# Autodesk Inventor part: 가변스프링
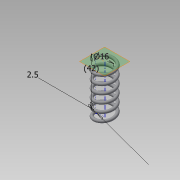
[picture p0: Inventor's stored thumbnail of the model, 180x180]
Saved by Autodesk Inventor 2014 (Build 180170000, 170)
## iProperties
Created: 2015-05
Part Number: 가변스프링
Material: Generic
Document SubType Name: Modeling
Designer: Administrator
Density: 1 g/cm^3
Appearance: Default
Mass: 1.46191 g
Surface Area: 23.7467 cm^2
Volume: 1.46191 cm^3
Author: Administrator
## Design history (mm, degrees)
sketch "스케치1"
  geometry: L1 (0, 0)-(-8, 0); L2 (-8, 0)-(-8, 41.999); L3 (-8, 41.999)-(0, 41.999); L4 (0, 41.999)-(0, 0); C1 r 1.25 at (-8, 0)
  constraints: 8 end point, 2 parallel, 1 centre point, 1 coincident, 1 horizontal, 1 perpendicular
  dimensions: "d0" = 2.5 diameter of C1; "d1" = 16 diameter of L2 L4; "d2" = 41.99913 distance between parallel lines of L3 L1 (derived)
feature "코일1" pitch "d3" = 10; turns "d5" = 6; dims "d4" = 41.99913 (= d2), "d6" = 0, angle "d7" = 90 deg, angle "d8" = 90 deg, "d9" = 0, "d10" = 0
sketch "스케치2"
  geometry: L1 (9.25, 0)-(6.75, 0) reference; 1 further point
  constraints: 1 horizontal alignment
extrude "돌출1" cut sketch "스케치2" distance "d11" = 10; taper "d12" = 0 deg
node "작업 평면1"
sketch "스케치3"
  geometry: L1 (-9.25, 0)-(-6.75, 0) reference; 1 further point
  constraints: 1 horizontal alignment
extrude "돌출2" cut sketch "스케치3" distance "d13" = 10; taper "d14" = 0 deg
node "솔리드1"
node "절단 모서리 투영1"
node "절단 모서리 투영2"
